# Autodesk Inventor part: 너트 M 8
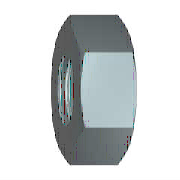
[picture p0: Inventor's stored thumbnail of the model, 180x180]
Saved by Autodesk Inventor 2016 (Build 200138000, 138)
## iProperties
IsCustomPart: 1
Created: 2012-02
Part Number: 너트 M 8
Material: 강철, 연강
Description: 6각 너트 및 6각 가는 너트
Document SubType Name: Modeling
Standard: KS B 1012
Designer: mduedu
Standards Organization: KS
Language: ko-KR
Size Designation: M 8
Categories: <MemberInstance><Categories><Category DisplayName="조임쇠" InternalName="e4da775c-781d-43d5-af7c-5136215cf5a6" Mnemonic="FSTN"><Category DisplayName="너트" InternalN
Density: 1 g/cm^3
Appearance: 강철
Author: mduedu
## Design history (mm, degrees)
sketch "스케치1"
  geometry: L1 (-7.506, 0)-(-3.753, 6.5); L2 (-3.753, 6.5)-(3.753, 6.5); L3 (3.753, 6.5)-(7.506, 0); L4 (7.506, 0)-(3.753, -6.5); L5 (3.753, -6.5)-(-3.753, -6.5); L6 (-3.753, -6.5)-(-7.506, 0); 2 further points
  constraints: 12 end point, 1 coincident, 1 horizontal, 11 other
  dimensions: "d0" = 15.01111 distance of L3.end L1.start (= 1.1547 x SW)
extrude "본체" new body sketch "스케치1" distance "d1" = 5 (= KOH); taper "d2" = 0 deg
sketch "스케치2"
  geometry: L1 (0, 3.753)-(0, 7.506) reference; L2 (0, 7.506)-(5, 7.506) reference; L3 (5, 3.753)-(5, 7.506) reference; L4 (-1, 0)-(6, 0) reference; L5 (0.581, 7.506)-(0, 6.5); L6 (4.419, 7.506)-(5, 6.5)
  constraints: 4 end point, 4 point on line
  dimensions: "d3" = 30 deg angle of L1 L5 (= ANG1); "d4" = 30 deg angle of L3 L6 (= ANG2); "d5" = 13 diameter of L5.end L4 (= SW0); "d6" = 13 diameter of L6.end L4 (= SW01)
revolve "모따기1" sketch "스케치2" stored, may be unused: angle "d7" = 90 deg
sketch "스케치3"
  geometry: A1 r 6.5 centre (0, 0) between (-3.25, -5.629) and (3.25, -5.629) reference; 1 further point
  constraints: 1 coincident
hole "스레드" sketch "스케치3" at (0, 0) diameter "d25" = 6.647; stored, may be unused: countersink angle "d29" = 82 deg, drill point angle "d31" = 118 deg; dims "d26" = 6, "d27" = 4, "d28" = 2, "d30" = 8
workaxis "Work Axis1"
workplane "Work Plane1"
body "Solid1"
chamfer "모따기2" distance "d8" = 0.67658 (= -0.5 x GD1 + 0.5 x NND); stored, may be unused: angle "d9" = 30 deg, second distance "d40" = 0.67658 (= -0.5 x GD1 + 0.5 x NND)
chamfer "모따기3" distance "d10" = 0.67658 (= -0.5 x GD1 + 0.5 x NND); stored, may be unused: angle "d11" = 30 deg, second distance "d41" = 0.67658 (= -0.5 x GD1 + 0.5 x NND)
other parameters: "ANG1" = 30 deg [user parameter; used in 1 equation term], "ANG2" = 30 deg [user parameter; used in 1 equation term], "NND" = 8 [user parameter; used in 4 equation terms], "KOH" = 5 [user parameter; used in 1 equation term], "SW" = 13 [user parameter; used in 4 equation terms], "SW0" = 13 (= SW) [user parameter; used in 1 equation term], "SW01" = 13 (= SW) [user parameter; used in 1 equation term], "GD1" = 6.64684 (computed from THREADDIA, PTC, TOA) [user parameter; used in 4 equation terms], "d13" = 0, "d14" = 0, "d39" = 0, "d42" = 0, "GUL" = 0.67658 (= 0.541266 x PTC) [user parameter], "TPU" = 8 (computed from PTC) [user parameter], "THREADDIA" = 8 [user parameter; used in 1 equation term], "TOA" = 30 deg [user parameter; used in 1 equation term], "PTC" = 1.25 [user parameter; used in 4 equation terms], "E0" = 15.015 (= 1.155 x SW) [user parameter], "GAL" = 0.67658 (= 0.541266 x PTC) [user parameter]
